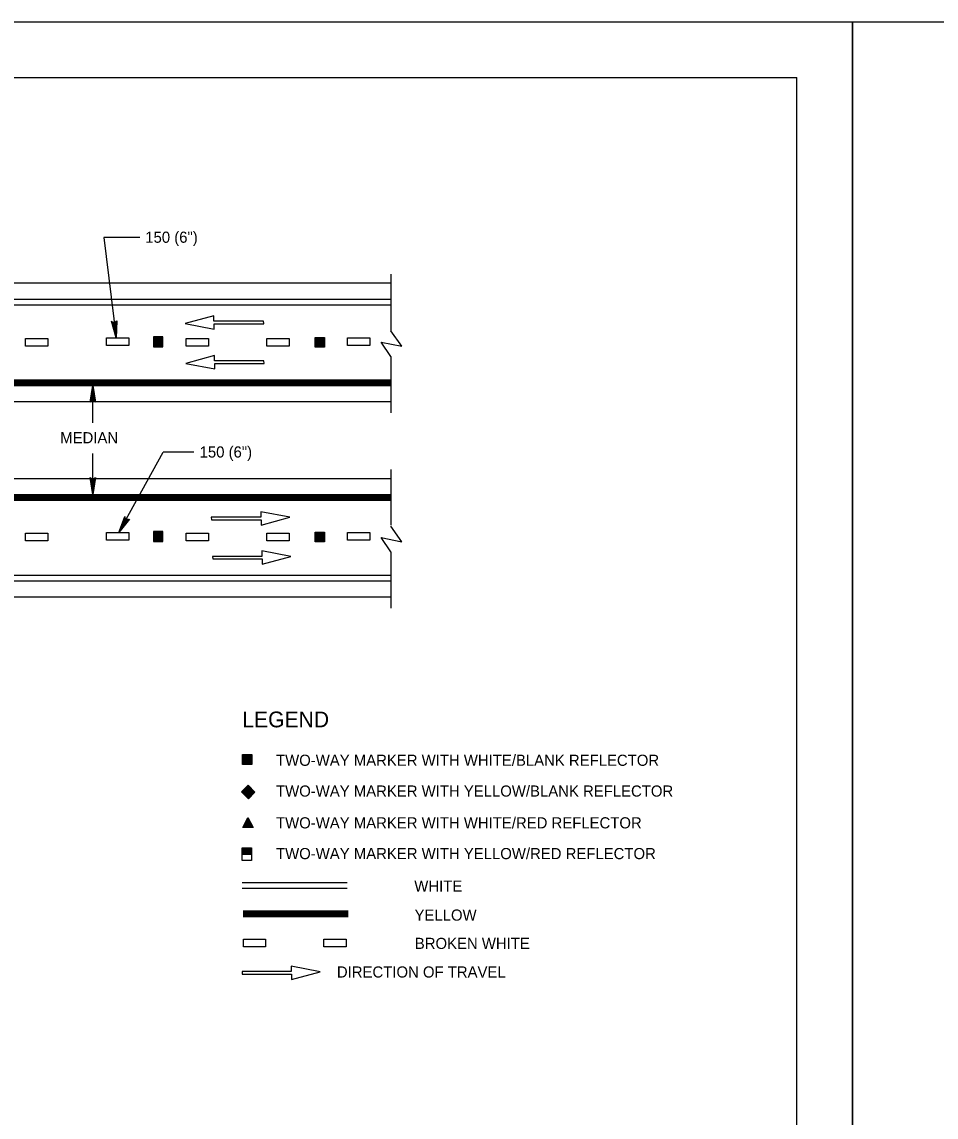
# Model space of a CAD drawing. Extents: x 639362 to 641108, y 298458 to 299646.
# Drawn here: x 639979.6 to 640225.9, y 299350.7 to 299645.6 of the extents above; entities that cross this region are included whole.
import ezdxf

# ---------------------------------------------------------------- set-up
doc = ezdxf.new("R2010")
doc.units = 0
for name, color, linetype in [('1', 7, 'Continuous'), ('2', 7, 'Continuous'), ('PLT-BNDY', 7, 'Continuous')]:
    doc.layers.add(name, color=color, linetype=linetype)

msp = doc.modelspace()

# ---------------------------------------------------------------- linework, layer by layer
at = {"layer": '1'}
for p in [(639402.31, 299630.63), (640188.31, 299066.63)]:
    msp.add_line(p, (640188.31, 299630.63), dxfattribs=at)
at = {"layer": '2'}
for p, q in [((640001.7, 299587.59), (640004.99, 299560.58)), ((640011.32, 299587.59), (640001.7, 299587.59)), ((640078.99, 299577.68), (640078.99, 299562.41)), ((639844.48, 299575.33), (640078.99, 299575.33)), ((639844.48, 299570.98), (640078.99, 299570.98)), ((639844.48, 299569.48), (640078.99, 299569.48)), ((640031.32, 299566.5), (640023.59, 299564.39)), ((640023.59, 299564.39), (640031.4, 299562.91)), ((640031.32, 299565.06), (640031.32, 299566.5)), ((640044.64, 299565.06), (640031.32, 299565.06)), ((640031.4, 299562.91), (640031.4, 299564.35)), ((640031.4, 299564.35), (640044.72, 299564.35)), ((640044.72, 299564.39), (640044.64, 299565.06)), ((640044.72, 299564.35), (640044.72, 299564.39)), ((640081.94, 299558.27), (640078.99, 299562.41)), ((639980.6, 299558.33), (639980.6, 299560.39)), ((639980.6, 299560.39), (639986.61, 299560.39)), ((639986.61, 299558.33), (639980.6, 299558.33)), ((639986.61, 299560.39), (639986.61, 299558.33)), ((640002.41, 299558.51), (640002.41, 299560.58)), ((640002.41, 299560.58), (640008.42, 299560.58)), ((640008.42, 299558.51), (640002.41, 299558.51)), ((640008.42, 299560.58), (640008.42, 299558.51)), ((640017.55, 299560.81), (640015.05, 299560.81)), ((640015.05, 299560.81), (640015.05, 299558.16)), ((640015.05, 299558.16), (640017.55, 299558.16)), ((640017.36, 299560.68), (640015.23, 299560.68)), ((640015.23, 299560.68), (640015.23, 299558.29)), ((640015.23, 299558.29), (640017.36, 299558.29)), ((640017.18, 299560.51), (640015.41, 299560.51)), ((640015.41, 299560.51), (640015.41, 299558.47)), ((640015.41, 299558.47), (640017.18, 299558.47)), ((640017, 299560.33), (640015.59, 299560.33)), ((640015.59, 299560.33), (640015.59, 299558.64)), ((640015.59, 299558.64), (640017, 299558.64)), ((640016.83, 299560.15), (640015.76, 299560.15)), ((640015.76, 299560.15), (640015.76, 299558.82)), ((640015.76, 299558.82), (640016.83, 299558.82)), ((640015.94, 299559.97), (640015.94, 299559)), ((640016.65, 299559.97), (640015.94, 299559.97)), ((640015.94, 299559), (640016.65, 299559)), ((640016.47, 299559.79), (640016.12, 299559.79)), ((640016.12, 299559.79), (640016.12, 299559.17)), ((640016.12, 299559.17), (640016.47, 299559.17)), ((640016.3, 299559.62), (640016.3, 299559.35)), ((640016.47, 299559.17), (640016.47, 299559.79)), ((640016.65, 299559), (640016.65, 299559.97)), ((640016.83, 299558.82), (640016.83, 299560.15)), ((640017, 299558.64), (640017, 299560.33)), ((640017.18, 299558.47), (640017.18, 299560.51)), ((640017.36, 299558.29), (640017.36, 299560.68)), ((640017.55, 299558.16), (640017.55, 299560.81)), ((640023.86, 299558.33), (640023.86, 299560.39)), ((640023.86, 299560.39), (640029.87, 299560.39)), ((640029.87, 299558.33), (640023.86, 299558.33)), ((640029.87, 299560.39), (640029.87, 299558.33)), ((640045.56, 299558.33), (640045.56, 299560.39)), ((640045.56, 299560.39), (640051.57, 299560.39)), ((640051.57, 299558.33), (640045.56, 299558.33)), ((640051.57, 299560.39), (640051.57, 299558.33)), ((640058.61, 299560.69), (640061.1, 299560.69)), ((640058.61, 299558.04), (640058.61, 299560.69)), ((640061.1, 299558.04), (640058.61, 299558.04)), ((640058.79, 299560.56), (640060.92, 299560.56)), ((640058.79, 299558.17), (640058.79, 299560.56)), ((640060.92, 299558.17), (640058.79, 299558.17)), ((640058.97, 299560.38), (640060.75, 299560.38)), ((640058.97, 299558.35), (640058.97, 299560.38)), ((640060.75, 299558.35), (640058.97, 299558.35)), ((640059.15, 299560.21), (640060.57, 299560.21)), ((640059.15, 299558.52), (640059.15, 299560.21)), ((640060.57, 299558.52), (640059.15, 299558.52)), ((640059.33, 299560.03), (640060.39, 299560.03)), ((640059.33, 299558.7), (640059.33, 299560.03)), ((640060.39, 299558.7), (640059.33, 299558.7)), ((640059.5, 299558.88), (640059.5, 299559.85)), ((640059.5, 299559.85), (640060.21, 299559.85)), ((640060.21, 299558.88), (640059.5, 299558.88)), ((640059.68, 299559.68), (640060.04, 299559.68)), ((640059.68, 299559.05), (640059.68, 299559.68)), ((640060.04, 299559.05), (640059.68, 299559.05)), ((640059.86, 299559.5), (640059.86, 299559.23)), ((640060.04, 299559.68), (640060.04, 299559.05)), ((640060.21, 299559.85), (640060.21, 299558.88)), ((640060.39, 299560.03), (640060.39, 299558.7)), ((640060.57, 299560.21), (640060.57, 299558.52)), ((640060.75, 299560.38), (640060.75, 299558.35)), ((640060.92, 299560.56), (640060.92, 299558.17)), ((640061.1, 299560.69), (640061.1, 299558.04)), ((640067.32, 299558.51), (640067.32, 299560.58)), ((640067.32, 299560.58), (640073.34, 299560.58)), ((640073.34, 299558.51), (640067.32, 299558.51)), ((640073.34, 299560.58), (640073.34, 299558.51)), ((640078.99, 299555.54), (640076.41, 299559.41)), ((640076.41, 299559.41), (640081.94, 299558.27)), ((640031.47, 299555.79), (640023.75, 299553.68)), ((640031.47, 299554.35), (640031.47, 299555.79)), ((640078.99, 299555.54), (640078.99, 299540.35)), ((640023.75, 299553.68), (640031.55, 299552.2)), ((640044.8, 299554.35), (640031.47, 299554.35)), ((640031.55, 299552.2), (640031.55, 299553.64)), ((640031.55, 299553.64), (640044.88, 299553.64)), ((640044.88, 299553.68), (640044.8, 299554.35)), ((640044.88, 299553.64), (640044.88, 299553.68)), ((639844.48, 299549.24), (640078.99, 299549.24)), ((639844.48, 299549.09), (640078.99, 299549.09)), ((639844.48, 299548.94), (640078.99, 299548.94)), ((639844.48, 299548.79), (640078.99, 299548.79)), ((639844.48, 299548.64), (640078.99, 299548.64)), ((639844.48, 299548.49), (640078.99, 299548.49)), ((639844.48, 299548.34), (640078.99, 299548.34)), ((639844.48, 299548.19), (640078.99, 299548.19)), ((639844.48, 299548.04), (640078.99, 299548.04)), ((639844.48, 299547.89), (640078.99, 299547.89)), ((639844.48, 299547.74), (640078.99, 299547.74)), ((639998.69, 299537.63), (639998.69, 299547.74)), ((639844.48, 299543.39), (640078.99, 299543.39)), ((639998.69, 299518.37), (639998.69, 299529.4)), ((640005.71, 299508.13), (640017.67, 299529.74)), ((640025.91, 299529.74), (640017.67, 299529.74)), ((639844.48, 299522.72), (640078.99, 299522.72)), ((640078.99, 299525.08), (640078.99, 299510.14)), ((639844.48, 299518.37), (640078.99, 299518.37)), ((639844.48, 299518.22), (640078.99, 299518.22)), ((639844.48, 299518.07), (640078.99, 299518.07)), ((639844.48, 299517.92), (640078.99, 299517.92)), ((639844.48, 299517.77), (640078.99, 299517.77)), ((639844.48, 299517.62), (640078.99, 299517.62)), ((639844.48, 299517.47), (640078.99, 299517.47)), ((639844.48, 299517.32), (640078.99, 299517.32)), ((639844.48, 299517.17), (640078.99, 299517.17)), ((639844.48, 299517.02), (640078.99, 299517.02)), ((639844.48, 299516.87), (640078.99, 299516.87)), ((640030.6, 299512.28), (640030.6, 299512.25)), ((640043.93, 299512.28), (640030.6, 299512.28)), ((640030.6, 299512.25), (640030.68, 299511.58)), ((640030.68, 299511.58), (640044.01, 299511.58)), ((640051.73, 299512.25), (640043.93, 299513.73)), ((640043.93, 299513.73), (640043.93, 299512.28)), ((640044.01, 299510.13), (640051.73, 299512.25)), ((640044.01, 299511.58), (640044.01, 299510.13)), ((639980.6, 299505.88), (639980.6, 299507.94)), ((639980.6, 299507.94), (639986.61, 299507.94)), ((639986.61, 299507.94), (639986.61, 299505.88)), ((640002.41, 299506.07), (640002.41, 299508.13)), ((640002.41, 299508.13), (640008.42, 299508.13)), ((640008.42, 299508.13), (640008.42, 299506.07)), ((640017.55, 299508.37), (640015.05, 299508.37)), ((640015.05, 299508.37), (640015.05, 299505.71)), ((640017.36, 299508.24), (640015.23, 299508.24)), ((640015.23, 299508.24), (640015.23, 299505.84)), ((640017.18, 299508.06), (640015.41, 299508.06)), ((640015.41, 299508.06), (640015.41, 299506.02)), ((640017, 299507.88), (640015.59, 299507.88)), ((640015.59, 299507.88), (640015.59, 299506.2)), ((640017, 299506.2), (640017, 299507.88)), ((640017.18, 299506.02), (640017.18, 299508.06)), ((640017.36, 299505.84), (640017.36, 299508.24)), ((640017.55, 299505.71), (640017.55, 299508.37)), ((640023.86, 299505.88), (640023.86, 299507.94)), ((640023.86, 299507.94), (640029.87, 299507.94)), ((640029.87, 299507.94), (640029.87, 299505.88)), ((640045.56, 299505.88), (640045.56, 299507.94)), ((640045.56, 299507.94), (640051.57, 299507.94)), ((640051.57, 299507.94), (640051.57, 299505.88)), ((640058.61, 299508.25), (640061.1, 299508.25)), ((640058.61, 299505.6), (640058.61, 299508.25)), ((640058.79, 299508.12), (640060.92, 299508.12)), ((640058.79, 299505.72), (640058.79, 299508.12)), ((640058.97, 299507.94), (640060.75, 299507.94)), ((640058.97, 299505.9), (640058.97, 299507.94)), ((640060.75, 299507.94), (640060.75, 299505.9)), ((640060.92, 299508.12), (640060.92, 299505.72)), ((640061.1, 299508.25), (640061.1, 299505.6)), ((640067.32, 299506.07), (640067.32, 299508.13)), ((640067.32, 299508.13), (640073.34, 299508.13)), ((640073.34, 299508.13), (640073.34, 299506.07)), ((640081.94, 299505.67), (640078.99, 299509.8)), ((639986.61, 299505.88), (639980.6, 299505.88)), ((640008.42, 299506.07), (640002.41, 299506.07)), ((640015.05, 299505.71), (640017.55, 299505.71)), ((640015.23, 299505.84), (640017.36, 299505.84)), ((640015.41, 299506.02), (640017.18, 299506.02)), ((640015.59, 299506.2), (640017, 299506.2)), ((640016.83, 299507.7), (640015.76, 299507.7)), ((640015.76, 299507.7), (640015.76, 299506.37)), ((640015.76, 299506.37), (640016.83, 299506.37)), ((640015.94, 299507.53), (640015.94, 299506.55)), ((640016.65, 299507.53), (640015.94, 299507.53)), ((640015.94, 299506.55), (640016.65, 299506.55)), ((640016.47, 299507.35), (640016.12, 299507.35)), ((640016.12, 299507.35), (640016.12, 299506.73)), ((640016.12, 299506.73), (640016.47, 299506.73)), ((640016.3, 299507.17), (640016.3, 299506.91)), ((640016.47, 299506.73), (640016.47, 299507.35)), ((640016.65, 299506.55), (640016.65, 299507.53)), ((640016.83, 299506.37), (640016.83, 299507.7)), ((640029.87, 299505.88), (640023.86, 299505.88)), ((640051.57, 299505.88), (640045.56, 299505.88)), ((640061.1, 299505.6), (640058.61, 299505.6)), ((640060.92, 299505.72), (640058.79, 299505.72)), ((640060.75, 299505.9), (640058.97, 299505.9)), ((640059.15, 299507.76), (640060.57, 299507.76)), ((640059.15, 299506.08), (640059.15, 299507.76)), ((640060.57, 299506.08), (640059.15, 299506.08)), ((640059.33, 299507.58), (640060.39, 299507.58)), ((640059.33, 299506.26), (640059.33, 299507.58)), ((640060.39, 299506.26), (640059.33, 299506.26)), ((640059.5, 299506.43), (640059.5, 299507.41)), ((640059.5, 299507.41), (640060.21, 299507.41)), ((640060.21, 299506.43), (640059.5, 299506.43)), ((640059.68, 299507.23), (640060.04, 299507.23)), ((640059.68, 299506.61), (640059.68, 299507.23)), ((640060.04, 299506.61), (640059.68, 299506.61)), ((640059.86, 299507.05), (640059.86, 299506.79)), ((640060.04, 299507.23), (640060.04, 299506.61)), ((640060.21, 299507.41), (640060.21, 299506.43)), ((640060.39, 299507.58), (640060.39, 299506.26)), ((640060.57, 299507.76), (640060.57, 299506.08)), ((640073.34, 299506.07), (640067.32, 299506.07)), ((640078.99, 299502.93), (640076.41, 299506.8)), ((640076.41, 299506.8), (640081.94, 299505.67)), ((640052.04, 299501.69), (640044.24, 299503.16)), ((640044.24, 299503.16), (640044.24, 299501.72)), ((640078.99, 299502.93), (640078.99, 299487.75)), ((640030.91, 299501.72), (640030.91, 299501.69)), ((640044.24, 299501.72), (640030.91, 299501.72)), ((640030.91, 299501.69), (640030.99, 299501.01)), ((640030.99, 299501.01), (640044.32, 299501.01)), ((640044.32, 299499.57), (640052.04, 299501.69)), ((640044.32, 299501.01), (640044.32, 299499.57)), ((639844.48, 299496.64), (640078.99, 299496.64)), ((639844.48, 299495.14), (640078.99, 299495.14)), ((639844.48, 299490.79), (640078.99, 299490.79)), ((640039.01, 299448.36), (640041.51, 299448.36)), ((640039.01, 299445.71), (640039.01, 299448.36)), ((640039.2, 299448.23), (640041.33, 299448.23)), ((640039.2, 299445.84), (640039.2, 299448.23)), ((640039.38, 299448.05), (640041.15, 299448.05)), ((640039.38, 299446.02), (640039.38, 299448.05)), ((640041.15, 299446.02), (640039.38, 299446.02)), ((640039.55, 299447.88), (640040.97, 299447.88)), ((640039.55, 299446.19), (640039.55, 299447.88)), ((640040.97, 299446.19), (640039.55, 299446.19)), ((640039.73, 299447.7), (640040.8, 299447.7)), ((640039.73, 299446.37), (640039.73, 299447.7)), ((640040.8, 299446.37), (640039.73, 299446.37)), ((640039.91, 299446.55), (640039.91, 299447.52)), ((640039.91, 299447.52), (640040.62, 299447.52)), ((640040.62, 299446.55), (640039.91, 299446.55)), ((640040.09, 299447.35), (640040.44, 299447.35)), ((640040.09, 299446.72), (640040.09, 299447.35)), ((640040.44, 299446.72), (640040.09, 299446.72)), ((640040.26, 299447.17), (640040.26, 299446.9)), ((640040.44, 299447.35), (640040.44, 299446.72)), ((640040.62, 299447.52), (640040.62, 299446.55)), ((640040.8, 299447.7), (640040.8, 299446.37)), ((640040.97, 299447.88), (640040.97, 299446.19)), ((640041.15, 299448.05), (640041.15, 299446.02)), ((640041.33, 299448.23), (640041.33, 299445.84)), ((640041.51, 299448.36), (640041.51, 299445.71)), ((640041.51, 299445.71), (640039.01, 299445.71)), ((640041.33, 299445.84), (640039.2, 299445.84)), ((640038.73, 299438.3), (640040.5, 299440.07)), ((640040.5, 299440.07), (640042.37, 299438.19)), ((640040.61, 299436.42), (640038.73, 299438.3)), ((640038.96, 299438.34), (640040.46, 299439.84)), ((640040.65, 299436.64), (640038.96, 299438.34)), ((640039.21, 299438.34), (640040.46, 299439.59)), ((640040.65, 299436.9), (640039.21, 299438.34)), ((640039.46, 299438.34), (640040.46, 299439.34)), ((640040.65, 299437.15), (640039.46, 299438.34)), ((640039.71, 299438.34), (640040.46, 299439.09)), ((640040.65, 299437.4), (640039.71, 299438.34)), ((640039.96, 299438.34), (640040.46, 299438.84)), ((640040.65, 299437.65), (640039.96, 299438.34)), ((640040.21, 299438.34), (640040.46, 299438.59)), ((640040.65, 299437.9), (640040.21, 299438.34)), ((640040.46, 299439.84), (640042.15, 299438.15)), ((640040.46, 299439.59), (640041.91, 299438.15)), ((640040.46, 299439.34), (640041.65, 299438.15)), ((640040.46, 299439.09), (640041.4, 299438.15)), ((640040.46, 299438.84), (640041.15, 299438.15)), ((640040.46, 299438.59), (640040.9, 299438.15)), ((640040.46, 299438.34), (640040.65, 299438.15)), ((640042.37, 299438.19), (640040.61, 299436.42)), ((640042.15, 299438.15), (640040.65, 299436.64)), ((640041.91, 299438.15), (640040.65, 299436.9)), ((640041.65, 299438.15), (640040.65, 299437.15)), ((640041.4, 299438.15), (640040.65, 299437.4)), ((640041.15, 299438.15), (640040.65, 299437.65)), ((640040.9, 299438.15), (640040.65, 299437.9)), ((640039.08, 299428.67), (640040.47, 299431.44)), ((640039.24, 299428.76), (640040.47, 299431.22)), ((640040.47, 299431.44), (640041.86, 299428.66)), ((640040.47, 299431.22), (640041.7, 299428.76)), ((640041.86, 299428.66), (640039.08, 299428.67)), ((640041.7, 299428.76), (640039.24, 299428.76)), ((640039.4, 299428.86), (640040.47, 299431)), ((640041.54, 299428.86), (640039.4, 299428.86)), ((640039.56, 299428.96), (640040.47, 299430.78)), ((640041.38, 299428.96), (640039.56, 299428.96)), ((640039.72, 299429.06), (640040.48, 299430.55)), ((640041.22, 299429.06), (640039.72, 299429.06)), ((640039.88, 299429.16), (640040.47, 299430.34)), ((640041.06, 299429.16), (640039.88, 299429.16)), ((640040.04, 299429.26), (640040.47, 299430.11)), ((640040.9, 299429.26), (640040.04, 299429.26)), ((640040.2, 299429.36), (640040.47, 299429.89)), ((640040.74, 299429.36), (640040.2, 299429.36)), ((640040.36, 299429.46), (640040.47, 299429.67)), ((640040.58, 299429.46), (640040.36, 299429.46)), ((640040.47, 299431), (640041.54, 299428.86)), ((640040.47, 299430.78), (640041.38, 299428.96)), ((640040.47, 299430.34), (640041.06, 299429.16)), ((640040.47, 299430.11), (640040.9, 299429.26)), ((640040.47, 299429.89), (640040.74, 299429.36)), ((640040.47, 299429.67), (640040.58, 299429.46)), ((640040.48, 299430.55), (640041.22, 299429.06)), ((640038.95, 299423.19), (640041.45, 299423.19)), ((640038.95, 299421.49), (640038.95, 299423.19)), ((640039.14, 299423.11), (640041.27, 299423.11)), ((640039.14, 299421.57), (640039.14, 299423.11)), ((640039.32, 299422.99), (640041.09, 299422.99)), ((640039.32, 299421.69), (640039.32, 299422.99)), ((640039.49, 299422.88), (640040.91, 299422.88)), ((640039.49, 299421.8), (640039.49, 299422.88)), ((640039.67, 299422.76), (640040.74, 299422.76)), ((640039.67, 299421.91), (640039.67, 299422.76)), ((640039.85, 299422.03), (640039.85, 299422.65)), ((640039.85, 299422.65), (640040.56, 299422.65)), ((640040.03, 299422.54), (640040.38, 299422.54)), ((640040.03, 299422.14), (640040.03, 299422.54)), ((640040.2, 299422.43), (640040.2, 299422.25)), ((640040.38, 299422.54), (640040.38, 299422.14)), ((640040.56, 299422.65), (640040.56, 299422.03)), ((640040.74, 299422.76), (640040.74, 299421.91)), ((640040.91, 299422.88), (640040.91, 299421.8)), ((640041.09, 299422.99), (640041.09, 299421.69)), ((640041.27, 299423.11), (640041.27, 299421.57)), ((640041.45, 299423.19), (640041.45, 299421.49)), ((640041.45, 299421.49), (640038.95, 299421.49)), ((640041.27, 299421.57), (640039.14, 299421.57)), ((640041.09, 299421.69), (640039.32, 299421.69)), ((640040.91, 299421.8), (640039.49, 299421.8)), ((640040.74, 299421.91), (640039.67, 299421.91)), ((640040.56, 299422.03), (640039.85, 299422.03)), ((640040.38, 299422.14), (640040.03, 299422.14)), ((640067.17, 299413.8), (640038.88, 299413.8)), ((640067.17, 299412.3), (640038.88, 299412.3)), ((640067.46, 299406.18), (640039.18, 299406.18)), ((640067.46, 299406.03), (640039.18, 299406.03)), ((640067.46, 299405.88), (640039.18, 299405.88)), ((640067.46, 299405.73), (640039.18, 299405.73)), ((640067.46, 299405.58), (640039.18, 299405.58)), ((640067.46, 299405.43), (640039.18, 299405.43)), ((640067.46, 299405.28), (640039.18, 299405.28)), ((640067.46, 299405.13), (640039.18, 299405.13)), ((640067.46, 299404.98), (640039.18, 299404.98)), ((640067.46, 299404.83), (640039.18, 299404.83)), ((640067.46, 299404.68), (640039.18, 299404.68)), ((640039.24, 299396.59), (640039.24, 299398.66)), ((640039.24, 299398.66), (640045.25, 299398.66)), ((640045.25, 299396.59), (640039.24, 299396.59)), ((640045.25, 299398.66), (640045.25, 299396.59)), ((640060.94, 299396.59), (640060.94, 299398.66)), ((640060.94, 299398.66), (640066.95, 299398.66)), ((640066.95, 299396.59), (640060.94, 299396.59)), ((640066.95, 299398.66), (640066.95, 299396.59)), ((640052.16, 299389.9), (640038.91, 299389.9)), ((640038.91, 299389.9), (640038.91, 299389.2)), ((640059.96, 299389.87), (640052.16, 299391.34)), ((640052.16, 299391.34), (640052.16, 299389.9)), ((640038.91, 299389.2), (640052.24, 299389.2)), ((640052.24, 299387.75), (640059.96, 299389.87)), ((640052.24, 299389.2), (640052.24, 299387.75))]:
    msp.add_line(p, q, dxfattribs=at)
for points in [[(640005.01, 299564.93), (640004.72, 299564.74), (640004.99, 299560.58), (640005.01, 299564.93), (640005.17, 299565.17), (640004.99, 299560.58), (640004.29, 299564.68), (640003.96, 299564.79), (640004.99, 299560.58), (640003.73, 299565), (640003.96, 299564.79)], [(639998.14, 299543.42), (639998.45, 299543.58), (639998.69, 299547.74), (639998.14, 299543.42), (639997.95, 299543.2), (639998.69, 299547.74), (639998.89, 299543.59), (639999.2, 299543.44), (639998.69, 299547.74), (639999.4, 299543.2), (639999.2, 299543.44)], [(639999.23, 299522.69), (639998.92, 299522.53), (639998.69, 299518.37), (639999.23, 299522.69), (639999.42, 299522.91), (639998.69, 299518.37), (639998.48, 299522.53), (639998.17, 299522.68), (639998.69, 299518.37), (639997.97, 299522.91), (639998.17, 299522.68)], [(640008.27, 299511.65), (640007.92, 299511.66), (640005.71, 299508.13), (640008.27, 299511.65), (640008.55, 299511.75), (640005.71, 299508.13), (640007.54, 299511.86), (640007.34, 299512.15), (640005.71, 299508.13), (640007.28, 299512.45), (640007.34, 299512.15)]]:
    msp.add_lwpolyline(points, dxfattribs=at)
msp.add_lwpolyline([(640038.95, 299421.49), (640041.45, 299421.49), (640041.45, 299419.8), (640038.95, 299419.8)], close=True, dxfattribs=at)
at = {"layer": 'PLT-BNDY'}
for points in [[(639362.31, 299645.63), (640203.31, 299645.63), (640203.31, 299051.63), (639362.31, 299051.63)], [(640203.31, 299645.63), (641044.31, 299645.63), (641044.31, 299051.63), (640203.31, 299051.63)]]:
    msp.add_lwpolyline(points, close=True, dxfattribs=at)

# ---------------------------------------------------------------- texts
at = {"layer": '2'}
for s, height, p in [('150 (6")', 3, (640012.82, 299586.15)), ('MEDIAN', 3, (639989.91, 299532.16)), ('150 (6")', 3, (640027.46, 299528.32)), ('LEGEND', 4.25, (640038.96, 299455.68)), ('TWO-WAY MARKER WITH WHITE/BLANK REFLECTOR', 3, (640048.05, 299445.31)), ('TWO-WAY MARKER WITH YELLOW/BLANK REFLECTOR', 3, (640048.05, 299437.02)), ('TWO-WAY MARKER WITH WHITE/RED REFLECTOR', 3, (640048.05, 299428.46)), ('TWO-WAY MARKER WITH YELLOW/RED REFLECTOR', 3, (640048.05, 299420.18)), ('WHITE', 3, (640085.29, 299411.42)), ('YELLOW', 3, (640085.36, 299403.62)), ('BROKEN WHITE', 3, (640085.43, 299396)), ('DIRECTION OF TRAVEL', 3, (640064.44, 299388.3))]:
    msp.add_text(s, height=height, dxfattribs=at).set_placement(p)

doc.saveas('drawing.dxf')
